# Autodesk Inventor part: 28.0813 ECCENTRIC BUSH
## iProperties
Created: 2009-01
Part Number: 28.0813 ECCENTRIC BUSH
Document SubType Name: Modeling
Designer: Administrator
Density: 7.85 g/cm^3
Material: Steel
Mass: 60.1117 g
Surface Area: 49.3109 cm^2
Volume: 7.65754 cm^3
Author: Administrator
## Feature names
1. Base1
